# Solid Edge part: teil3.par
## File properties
Author: Susi
Template: Normal.par
Last saved by: Susi
Revision: 1
Application: Solid Edge
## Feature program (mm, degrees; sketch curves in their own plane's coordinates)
sketch for "unnamed Protrusion 1" plane through (0, 0, 0) normal (0, 0, 1) x-axis (1, 0, 0)
extrude "unnamed Protrusion 1" add finite 10 along -normal
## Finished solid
Body 1: solid body, 3 faces, 2 edges, 0 vertices.
  Faces by surface: plane 2, cylinder 1
  Edges by curve: circle 2
Bounding box of the edges (mm): 8.000 x 8.000 x 10.000, from (-4, -4, -10) to (4, 4, 0).
Cylindrical faces by radius (mm): R4 x1
Planar faces by outward normal: +z 1, -z 1
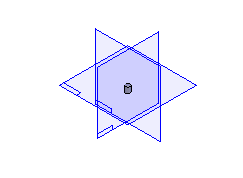
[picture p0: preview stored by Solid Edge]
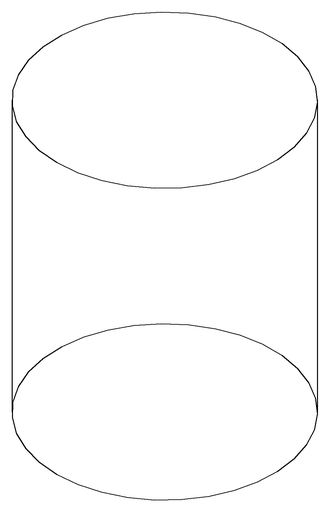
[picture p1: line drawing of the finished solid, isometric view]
